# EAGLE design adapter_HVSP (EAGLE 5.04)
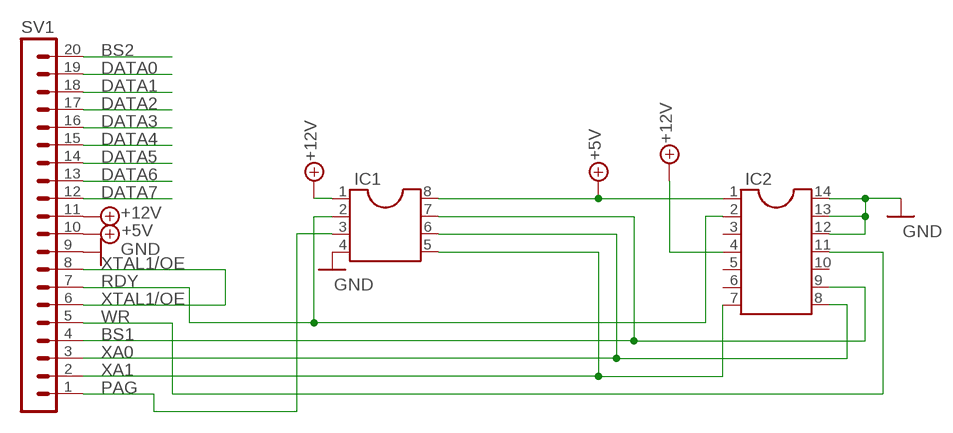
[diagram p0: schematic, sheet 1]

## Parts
IC1  DIL8S  [SOCKED-08]
IC2  DIL14S  [SOCKED-14]
SV1  MA20-1  [MA20-1]

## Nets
+5V: IC1.8 IC2.1 SV1.10
+12V: IC1.1 IC2.4 SV1.11
BS1: IC1.7 IC2.9 SV1.4
BS2: SV1.20
DATA0: SV1.19
DATA1: SV1.18
DATA2: SV1.17
DATA3: SV1.16
DATA4: SV1.15
DATA5: SV1.14
DATA6: SV1.13
DATA7: SV1.12
GND: IC1.4 IC2.12 IC2.13 IC2.14 SV1.9
PAG: IC1.3 SV1.1
RDY: IC1.2 IC2.2 SV1.7
WR: IC2.11 SV1.5
XA0: IC1.6 IC2.8 SV1.3
XA1: IC1.5 IC2.7 SV1.2
XTAL1/OE: SV1.6 SV1.8
Unconnected: IC2.3 IC2.5 IC2.6 IC2.10

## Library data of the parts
IC1 = ic-package:DIL8: Dual In Line
IC2 = ic-package:DIL14: Dual In Line
SV1 = con-lstb:MA20-1: PIN HEADER

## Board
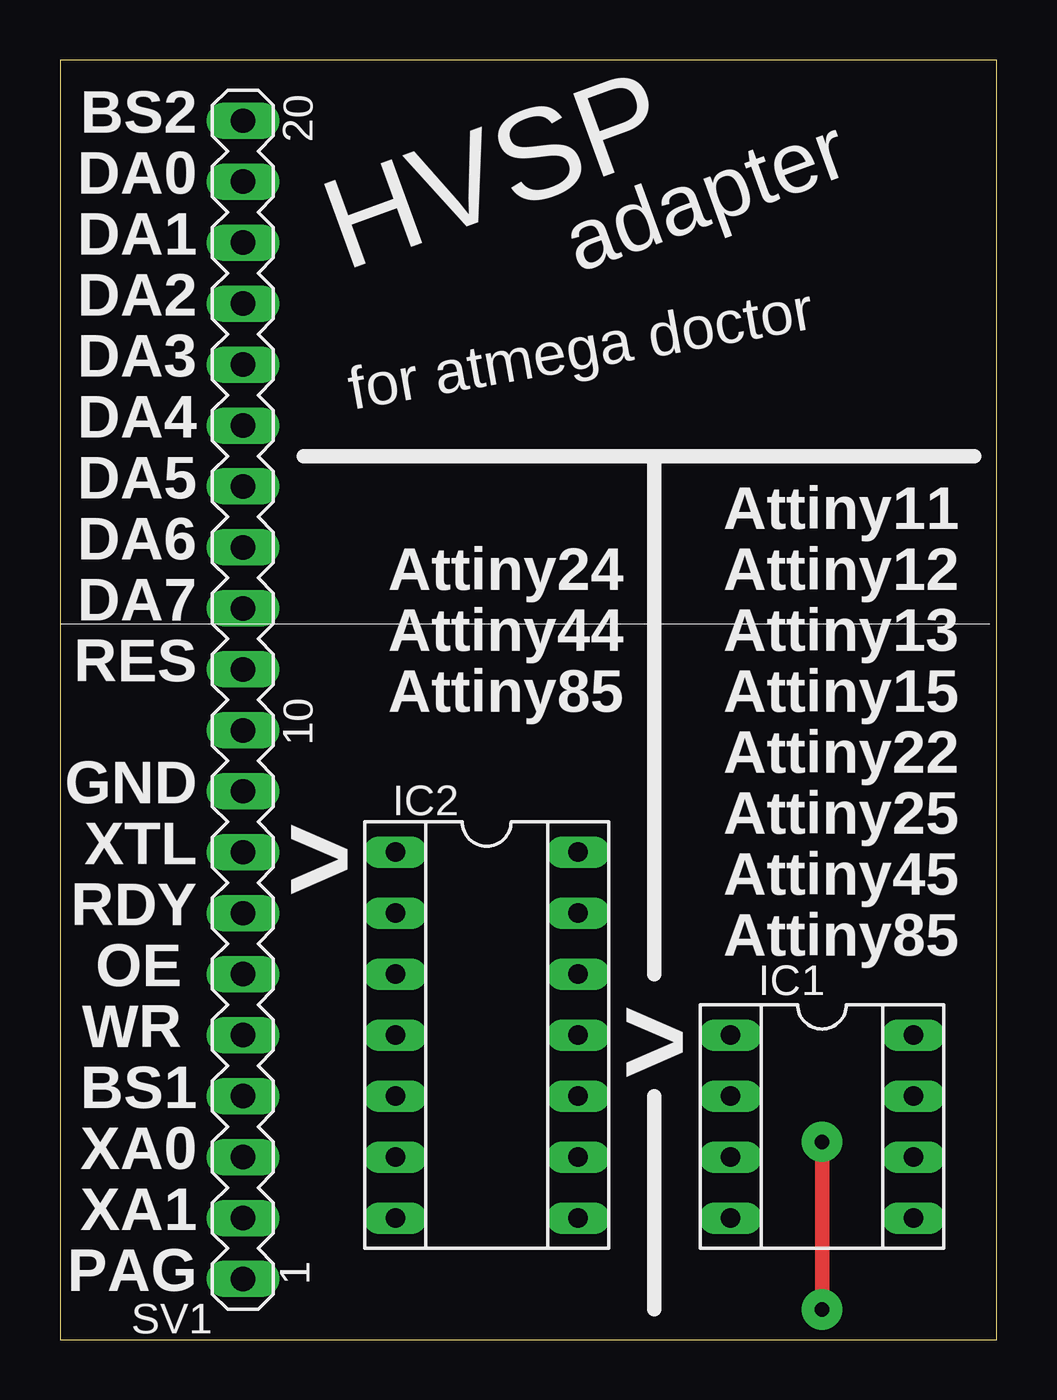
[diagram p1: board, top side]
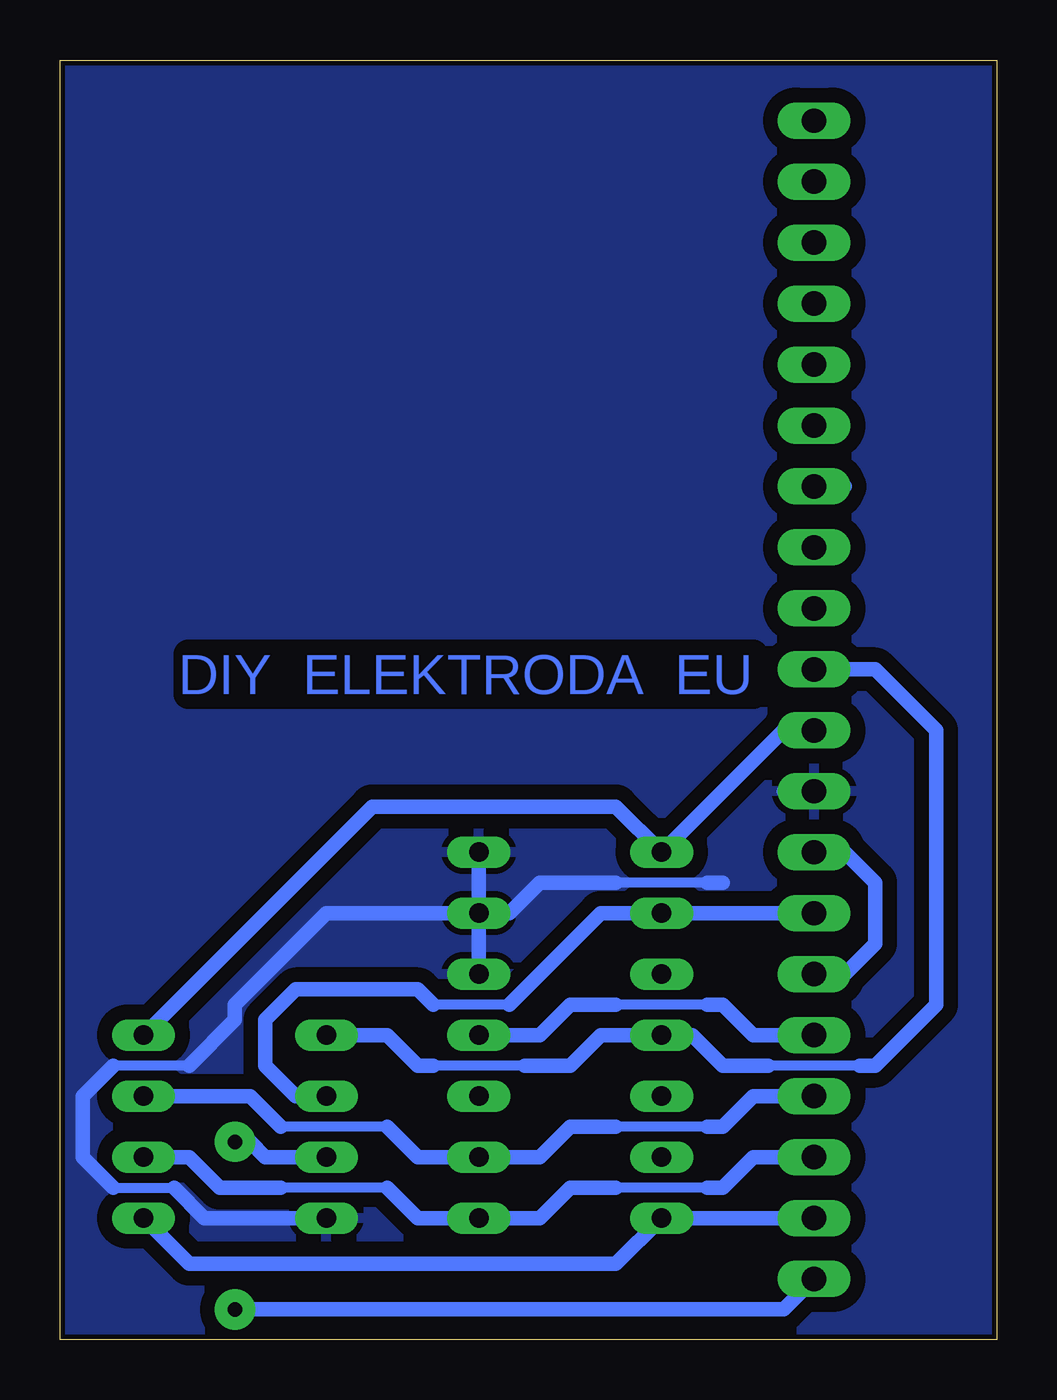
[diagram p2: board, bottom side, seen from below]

Size 39.04 x 53.33 mm. Coordinates in mm from the lower left corner, seen from the top.
Outline: 0,0 39.04,0 39.04,53.33 0,53.33 0,0
Copper layers (1*16): Top 0.035mm / dielectric 1.5mm / Bottom 0.035mm
Design rules "default *": minimum track width 10mil, minimum drill 24mil, track to track 24mil, track to pad 24mil, pad to pad 8mil, via to via 8mil, smd to smd 8mil, copper to edge 8mil, drill to drill 8mil, minimum pad ring 10mil, minimum via ring 8mil, stop-mask expansion 4mil, vias tented up to drill 0mil, thermal gap 10mil

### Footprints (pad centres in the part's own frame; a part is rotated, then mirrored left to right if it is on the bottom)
SOCKED-08 = drill 0.813 long: 1 -3.81,-3.81; 2 -1.27,-3.81; 3 1.27,-3.81; 4 3.81,-3.81; 5 3.81,3.81; 6 1.27,3.81; 7 -1.27,3.81; 8 -3.81,3.81
SOCKED-14 = drill 0.813 long: 1 -7.62,-3.81; 2 -5.08,-3.81; 3 -2.54,-3.81; 4 0,-3.81; 5 2.54,-3.81; 6 5.08,-3.81; 7 7.62,-3.81; 8 7.62,3.81; 9 5.08,3.81; 10 2.54,3.81; 11 0,3.81; 12 -2.54,3.81; 13 -5.08,3.81; 14 -7.62,3.81
MA20-1 = drill 1.016 long: 1 -24.13,0; 2 -21.59,0; 3 -19.05,0; 4 -16.51,0; 5 -13.97,0; 6 -11.43,0; 7 -8.89,0; 8 -6.35,0; 9 -3.81,0; 10 -1.27,0; 11 1.27,0; 12 3.81,0; 13 6.35,0; 14 8.89,0; 15 11.43,0; 16 13.97,0; 17 16.51,0; 18 19.05,0; 19 21.59,0; 20 24.13,0

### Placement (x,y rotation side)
IC1  31.75,8.89 270 top
IC2  17.78,12.7 270 top
SV1  7.62,26.67 90 top

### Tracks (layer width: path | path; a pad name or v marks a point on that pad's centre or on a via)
+5V
  Bottom 0.61: SV1.10 8.89,25.4 IC2.1 15.88,22.23 26.04,22.23 IC1.8
+12V
  Bottom 0.406: 19.68,11.43 23.5,11.43 | 5.71,11.43 9.53,11.43
  Bottom 0.61: 19.68,11.43 17.78,11.43 16.51,12.7 IC2.4 12.7,12.7 11.43,11.43 9.53,11.43 | 23.5,11.43 24.13,11.43 25.4,12.7 IC1.1 | SV1.11 5.08,27.94 2.54,25.4 2.54,13.97 5.08,11.43 5.71,11.43
BS1
  Bottom 0.406: 12.06,8.89 15.88,8.89 | 25.4,8.89 29.84,8.89
  Bottom 0.61: SV1.4 10.16,10.16 11.43,8.89 12.06,8.89 | 15.88,8.89 17.78,8.89 19.05,7.62 IC2.9 24.13,7.62 25.4,8.89 | 29.84,8.89 31.11,10.16 IC1.7
DATA5
  Bottom 0.61: 6.35,35.56 SV1.14
GND
  Bottom 0.406: 36.83,6.35 34.29,6.35 | 33.66,11.43 36.83,11.43 | 12.06,19.05 15.88,19.05
  Bottom 0.61: IC2.13 IC2.14 | IC2.13 IC2.12 | IC1.4 33.02,5.08 34.29,6.35 | 36.83,6.35 38.1,7.62 38.1,10.16 36.83,11.43 | 33.66,11.43 31.75,13.34 31.75,13.97 27.94,17.78 IC2.13 | SV1.9 8.89,22.86 | 12.06,19.05 11.43,19.05 | 15.88,19.05 19.05,19.05 20.32,17.78 IC2.13
  pour Bottom: 0,53.34 38.73,53.34 38.73,0 0,0
PAG  (via drill 0.6 pad 1.68)
  Top 0.61: v31.75,1.27 v31.75,8.26
  Bottom 0.61: SV1.1 8.89,1.27 v31.75,1.27 | IC1.3 30.48,7.62 31.11,8.26 v31.75,8.26
RDY
  Bottom 0.406: 20.32,13.97 23.5,13.97
  Bottom 0.61: IC1.2 29.21,10.16 30.48,11.43 30.48,13.34 29.21,14.61 24.13,14.61 23.5,13.97 | 20.32,13.97 16.51,17.78 IC2.2 SV1.7
WR
  Bottom 0.406: 12.06,13.97 15.88,13.97
  Bottom 0.61: IC2.11 19.05,12.7 17.78,13.97 15.88,13.97 | 12.06,13.97 11.43,13.97 10.16,12.7 SV1.5
XA0
  Bottom 0.406: 12.06,6.35 15.88,6.35 | 25.4,6.35 29.84,6.35
  Bottom 0.61: SV1.3 10.16,7.62 11.43,6.35 12.06,6.35 | 15.88,6.35 17.78,6.35 19.05,5.08 IC2.8 24.13,5.08 25.4,6.35 | 29.84,6.35 32.38,6.35 33.66,7.62 IC1.6
XA1
  Bottom 0.61: SV1.2 IC2.7 15.88,3.17 33.66,3.17 IC1.5
XTAL1/OE
  Bottom 0.61: SV1.8 6.35,20.32 5.08,19.05 5.08,16.51 6.35,15.24 SV1.6

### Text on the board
Bottom: DIY ELEKTRODA EU
tPlace: BS2 | DA0 | DA1 | HVSP | DA2 | adapter | DA3 | DA4 | for atmega doctor | DA5 | Attiny11 | DA6 | Attiny24 | Attiny12 | DA7 | Attiny44 | Attiny13 | RES | Attiny85 | Attiny15 | Attiny22 | GND | Attiny25 | XTL | ^ | Attiny45 | RDY | Attiny85 | OE | WR | ^ | BS1 | XA0 | XA1 | PAG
